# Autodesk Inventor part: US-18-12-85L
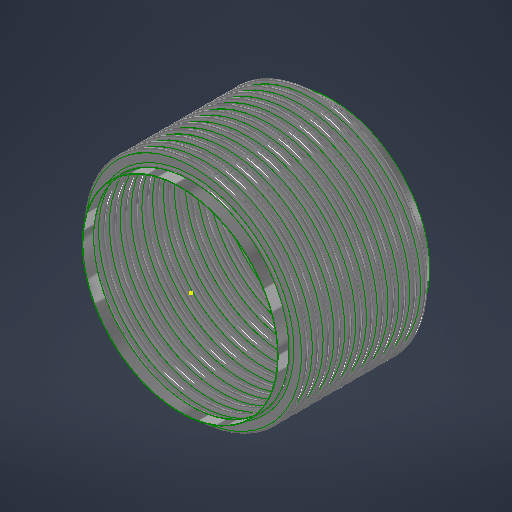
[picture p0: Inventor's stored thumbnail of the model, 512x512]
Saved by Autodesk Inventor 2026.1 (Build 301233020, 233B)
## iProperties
Category: 18 GA (0.048 THICK)
RuleStatus: InUse
Created: 2026-07
Part Number: US-18-12-85L
Project: =STOCK BELLOWS: <Stock Number><SFILL>
Material: ASTM A240-304
Description: =STOCK BELLOWS: <Stock Number>, <SID_> I.D., <SOD_> O.D., <SPLY_> PLY, <Category>, <SNET_CONS> CONS.<PITCH_><STANGENT_> TANGENT<SFILL>
Document SubType Name: Sheet Metal
Designer: LC
Stock Number: U.S-18-12-85L
Surface Area: 659.127 cm^2
Volume: 56.61 cm^3
Sheet Metal Rule: Default
Appearance: STAINLESS STEEL
NET_TUBE: 3.428
COUNTER: 1.500
PBAR: 1.214
PSET: 5.356
PLY: 2
CONS: 2
THK: 0.036
ID: 4.500
OD: 5.500
CONS_: 2
TANGENT: 0.500
PITCH: 0.375
BELLOWS_UPSET: 0.000
NET_CONS: 2
S_CONS: 0
Description_Units: 0
ID_M: 114.30 mm
OD_M: 139.70 mm
THK_M: 0.91 mm
ID_U: 4.500 in
OD_U: 5.500 in
THK_U: 0.036 in
TANGENT2: 0.500
d79: 1.000
d82: 1.000
d83: 26.000
d84: 24.000
d80: 2.571
d81: 10
SID: 2.375
SCONS_: 12
SPITCH: 0.250
SBELLOWS_UPSET: 0.000
SNET_CONS: 12
SS_CONS: 0
SCONS: 8
d174: 8
d177: 0.018
d178: 2.375
d179: 3.000
d180: 0.375
d181: 1.000
d182: 0.000
d190: 8
d191: 1
d192: 1
d193: 8
d194: 0
PART_NUMBER: U.S-18-12-85L
PRESSURE: 85
SIZE: 18.00
STANGENT_: 1.000
d214: 8
d217: 0.030
d218: 6.625
d219: 8.125
d220: 0.500
d221: 1.000
d222: 0.000
d230: 8
d231: 1
d232: 1
d233: 8
d234: 0
STANGENT: 4.000
SPLY_: 1
STHK_: 0.048
SID_: 18.000
SOD_: 20.500
SPITCH_: 1.000
STANGENT__: 1.000
SBELLOWS_UPSET_: 0.000
SDIFF_TAN: 1.000
TAN_TO_TAN: 0.750 in
d252: 2
d275: 2
d287: 0.050
d289: 0.500
d290: 0.000
d263: 2
d265: 1
d268: 2
d269: 0
d286: 2
d288: 1
d291: 2
d292: 0
SOD_NECK: 18 1/8
CFILL: .
SFILL: .
PITCH_: =, <SPITCH_> PITCH,
SREROLL: 0.750
MATTABLE: 20 GA (0.036 THICK)
MESH: ,
CSECT: 2
Author: LC
Keywords: 20 GA (0.036 THICK)
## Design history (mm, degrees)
sketch "Sketch2"
  geometry: L1 (0, -183.595)-(0, 600.956) reference; L2 (58.979, 0)-(57.15, 0); L3 (60.446, -1.467)-(66.554, -1.467); L4 (60.446, -3.296)-(66.554, -3.296); L5 (66.554, -8.058)-(60.446, -8.058); L6 (66.554, -6.229)-(60.446, -6.229); L7 (58.979, -9.525)-(57.15, -9.525); L8 (60.446, 0)-(60.446, -9.525); L9 (66.554, -4.762)-(69.85, -4.763); L10 (57.15, 0)-(57.15, -9.525); L11 (20.376, 102.841)-(20.376, 101.926); L12 (58.262, 488.877)-(58.262, 349.177); L13 (58.262, 479.352)-(58.262, 339.652); L14 (93.133, -58.817)-(93.133, -71.517); L15 (118.746, -66.401)-(118.746, -66.401); L16 (66.554, -6.229)-(66.554, -8.058); L17 (60.446, -6.229)-(60.446, -8.058); L18 (60.446, -7.144)-(66.554, -7.144); L19 (69.85, 0)-(69.85, -9.525); L20 (-66.554, -6.229)-(-66.554, -8.058); L21 (-66.554, -1.467)-(-60.446, -1.467); L22 (-66.554, -3.296)-(-60.446, -3.296); L23 (-60.446, -6.229)-(-66.554, -6.229); L24 (-66.554, -7.144)-(-60.446, -7.144); L25 (-60.446, -8.058)-(-66.554, -8.058); L26 (-60.446, -6.229)-(-60.446, -8.058); L27 (-57.15, -2.522)-(-57.15, -12.047); L28 (-60.446, -4.763)-(-57.15, -4.763); L29 (-66.554, 3.828)-(-66.554, -9.525); L30 (-68.021, 0)-(-69.85, 0); L31 (-69.85, 0)-(-69.85, -9.525); L32 (-68.021, -9.525)-(-69.85, -9.525); A1 r 1.467 centre (60.446, 0) between (58.979, 0) and (60.446, -1.467); A2 r 3.296 centre (60.446, 0) between (57.15, 0) and (60.446, -3.296); A3 r 3.296 centre (66.554, -4.762) between (66.554, -8.058) and (66.554, -1.467); A4 r 1.467 centre (66.554, -4.762) between (66.554, -6.229) and (66.554, -3.296); A5 r 1.467 centre (60.446, -9.525) between (60.446, -8.058) and (58.979, -9.525); A6 r 3.296 centre (60.446, -9.525) between (60.446, -6.229) and (57.15, -9.525); A7 r 2.381 centre (66.554, -4.762) between (66.554, -7.144) and (68.936, -4.762); A8 r 2.381 centre (60.446, -9.525) between (60.446, -7.144) and (58.064, -9.525); A9 r 1.467 centre (-66.554, -9.525) between (-66.554, -8.058) and (-68.021, -9.525); A10 r 1.467 centre (-60.446, -4.763) between (-60.446, -6.229) and (-60.446, -3.296); A11 r 2.381 centre (-60.446, -4.763) between (-60.446, -7.144) and (-58.064, -4.763); A12 r 3.296 centre (-60.446, -4.763) between (-60.446, -8.058) and (-60.446, -1.467); A13 r 2.381 centre (-66.554, -9.525) between (-66.554, -7.144) and (-68.936, -9.525); A14 r 3.296 centre (-66.554, -9.525) between (-66.554, -6.229) and (-69.85, -9.525); A15 r 1.467 centre (-66.554, 0) between (-68.021, 0) and (-66.554, -1.467); A16 r 3.296 centre (-66.554, 0) between (-69.85, 0) and (-66.554, -3.296); 10 further points
  constraints: 62 end point, 38 point on circle, 20 tangent, 16 centre point, 12 parallel, 9 midpoint, 7 vertical, 6 coincident, 6 concentric, 6 point on line, 4 equal radius, 4 perpendicular, 3 horizontal, 1 collinear, 1 horizontal alignment, 10 other
  dimensions: "THK" = 0.9144 distance of L11.start L11.end; "ID" = 114.3 distance of L11.end point (20.376, -12.374); "OD" = 139.7 distance of L12.start L12.end; "PITCH" = 9.525 distance of L12.start L13.start; "TANGENT" = 12.7 distance of L14.start L14.end; "BELLOWS_UPSET" = 0 distance of L15.start L15.end; "d43" = 114.3 diameter of L10 L1 (= ID); "d44" = 139.7 diameter of L9.end L1 (= OD); "d45" = 1.8288 distance between parallel lines of L5 L6 (computed from THK, PLY); "d46" = 3.29565 radius of A3 (computed from PITCH, THK, PLY); "UPSET_PITCH" = 9.525 distance of L2.end L7.end (derived); "SIDEWALL_ANGLE" = 0 deg angle of L3 L9 (derived); "CON_GAP" = 2.9337 distance of point (60.446, -6.229) point (60.446, -3.296) (derived); "TAN1" = 3.74046 dimension on A8 (derived); "TAN2" = 3.74046 dimension on A7 (derived); "LEG1" = 6.1087 distance of L18.start L18.end (derived); "d278" = 1.8288 distance between parallel lines of L25 L23 (derived); "d279" = 3.29565 radius of A12 (derived); "d280" = 9.525 distance of L30.end L31.end (derived); "d281" = 360 deg dimension on L21 L28 (derived); "d282" = 2.9337 distance of point (-66.554, -6.229) point (-66.554, -3.296) (derived); "d283" = 3.74046 dimension on A13 (derived); "d284" = 3.74046 dimension on A11 (derived); "d285" = 6.1087 distance of L24.start L24.end (derived); "d293" = 114.3 diameter of L27 L1 (derived); "d294" = 139.7 diameter of L31 L1 (derived)
  node "Sketch Rectangular Pattern1" dims "d31" = 25.4, "ID" = 114.3
  node "Sketch Rectangular Pattern2" dims "d39" = 25.4, "PITCH" = 9.525
revolve "CONS" stored, may be unused: angle "d48" = 90 deg
node "BELLOW MIDPLANE"
pattern_linear "Rectangular Pattern2" dims "d52" = 9.525 (= UPSET_PITCH)
sketch "Sketch5"
  geometry: C1 r 58.979 at (0, 0) reference; C2 r 57.15 at (0, 0) reference
extrude "TANGENT" new body sketch "Sketch5" distance "d53" = 12.7 (= TANGENT); taper "d54" = 0 deg
revolve "SAMETAN" stored, may be unused: angle "d65" = 90 deg
revolve "DIFFTAN" stored, may be unused: angle "d70" = 90 deg
sketch "Sketch9"
  geometry: L1 (58.391, 0)-(-58.391, 0) reference; L2 (0, -17.78)-(0, 17.78) reference; L3 (41.708, 0)-(-41.708, 0); L4 (41.708, -11.906)-(41.708, 11.906); L5 (29.008, -11.906)-(29.008, 11.906); L6 (15.418, 11.906)-(15.418, -11.906); L7 (-29.008, -11.906)-(-29.008, 11.906); L8 (-41.708, -11.906)-(-41.708, 11.906); L9 (40.914, -11.906)-(40.914, 11.906); L10 (41.708, -11.906)-(40.914, -11.906); L11 (41.708, 11.906)-(40.914, 11.906); L12 (15.815, 11.906)-(15.022, 11.906); L13 (15.022, 11.906)-(15.022, -11.906); L14 (15.022, -11.906)-(15.815, -11.906); L15 (15.815, -11.906)-(15.815, 11.906); L16 (-15.815, 11.906)-(-15.815, -11.906); L17 (-15.418, 11.906)-(-15.418, -11.906); L18 (-15.815, -11.906)-(-15.022, -11.906); L19 (-15.022, -11.906)-(-15.022, 11.906); L20 (-15.022, 11.906)-(-15.815, 11.906); L21 (-41.708, -11.906)-(-40.914, -11.906); L22 (-40.914, -11.906)-(-40.914, 11.906); L23 (-40.914, 11.906)-(-41.708, 11.906); L24 (-41.708, 11.906)-(-41.708, -11.906); L25 (41.708, -0.397)-(-41.708, -0.397); L26 (-41.708, -0.397)-(-41.708, 0.397); L27 (-41.708, 0.397)-(41.708, 0.397); L28 (41.708, 0.397)-(41.708, -0.397); L29 (-41.708, 11.906)-(41.708, 11.906); L30 (41.708, 11.906)-(41.708, 12.7); L31 (41.708, 12.7)-(-41.708, 12.7); L32 (-41.708, 12.7)-(-41.708, 11.906); L33 (41.708, -11.906)-(-41.708, -11.906); L34 (-41.708, -11.906)-(-41.708, -12.7); L35 (-41.708, -12.7)-(41.708, -12.7); L36 (41.708, -12.7)-(41.708, -11.906); 30 further points
  constraints: 68 end point, 13 midpoint, 13 parallel, 8 horizontal, 7 perpendicular, 6 equal length, 3 point on line, 2 vertical, 14 other
  dimensions: "d115" = 23.8125 distance of L4.start L4.end (derived); "d116" = 12.7 distance between parallel lines of L4 L5 (derived); "d117" = 13.58962 distance between parallel lines of L5 L6 (derived); "d125" = 44.42645 distance between parallel lines of L7 L6 (derived); "d127" = 12.7 distance between parallel lines of L8 L7 (derived); "d128" = 26.28962 distance between parallel lines of L6 L4 (derived); "d130" = 83.41607 distance between parallel lines of L8 L4 (derived); "RULER_THK" = 0.79375 distance between parallel lines of L4 L9; "d135" = 0.79375 distance of L13.end L14.end (derived); "d138" = 30.83684 distance of L13.end L16.end (derived); "d143" = 0.79375 distance of L22.end L8.end (derived); "d144" = 0.79375 distance between parallel lines of L27 L25 (derived)
extrude "RULER" join sketch "Sketch9" distance "d149" = 0.79375 (derived); taper "d150" = 0 deg
extrude "BARS" join sketch "Sketch9" distance "d151" = 0.79375 (derived); taper "d152" = 0 deg
pattern_linear "Rectangular Pattern4" dims "d155" = 30.83684 (derived)
sketch "Sketch13"
  geometry: L1 (93.149, -52.467)-(93.149, -77.867); L2 (229.819, 0)-(228.6, 0); L3 (229.819, -25.4)-(228.6, -25.4); L4 (253.39, -19.66)-(235.56, -19.66); L5 (253.39, -18.44)-(235.56, -18.44); L6 (253.39, -12.7)-(260.35, -12.7); L7 (235.56, -5.74)-(253.39, -5.74); L8 (235.56, 0)-(235.56, -25.4); L9 (228.6, 0)-(228.6, -25.4); L10 (58.254, -220.206)-(58.254, -740.906); L11 (58.254, -245.606)-(58.254, -766.306); L12 (58.254, -296.406)-(58.254, -817.106); L13 (58.254, -321.806)-(58.254, -842.506); L14 (58.254, -347.206)-(58.254, -867.906); L15 (58.254, -372.606)-(58.254, -893.306); L16 (58.254, -398.006)-(58.254, -918.706); L17 (58.254, -271.006)-(58.254, -791.706); L18 (20.376, 103.145)-(20.376, 101.926); L19 (235.56, -6.96)-(253.39, -6.96); L20 (0, -1082.436)-(0, 300.742) reference; L21 (-46.99, 0)-(281.94, 0) reference; A1 r 5.74 centre (235.56, 0) between (229.819, 0) and (235.56, -5.74); A2 r 5.74 centre (235.56, -25.4) between (235.56, -19.66) and (229.819, -25.4); A3 r 6.96 centre (235.56, -25.4) between (235.56, -18.44) and (228.6, -25.4); A4 r 5.74 centre (253.39, -12.7) between (253.39, -18.44) and (253.39, -6.96); A5 r 6.96 centre (253.39, -12.7) between (253.39, -19.66) and (253.39, -5.74); A6 r 6.96 centre (235.56, 0) between (228.6, 0) and (235.56, -6.96); 6 further points; 1 other entity
  constraints: 38 end point, 15 point on circle, 9 tangent, 6 centre point, 6 parallel, 5 vertical alignment, 4 point on line, 4 vertical, 3 coincident, 3 concentric, 2 collinear, 2 equal radius, 1 horizontal, 1 perpendicular, 23 other
  dimensions: "SBELLOWS_UPSET_" = 0 distance of point (118.762, -66.401) point (118.762, -66.401); "STOTAL_THK_BELLOW__" = 1.2192 distance between parallel lines of L4 L5 (derived); "d224" = 6.9596 radius of A5 (derived); "d225" = 25.4 distance of L2.end L3.end (derived); "SSIDEWALL_ANGLE_" = 360 deg dimension on L7 L6 (derived); "SSCON_GAP_" = 11.4808 distance of point (235.56, -18.44) point (235.56, -6.96) (derived); "d235" = 457.2 diameter of L9 L20 (derived); "d236" = 520.7 diameter of L6.end L20 (derived)
  node "Sketch Rectangular Pattern4" dims "d228" = 25.4
  node "Sketch Rectangular Pattern5" dims "d229" = 25.4
revolve "SBELLOW" stored, may be unused: angle "d197" = 90 deg
pattern_linear "Rectangular Pattern5" dims "d204" = 25.4 (derived)
revolve "STANGENT" stored, may be unused: angle "d240" = 90 deg
revolve "SSAMETAN" stored, may be unused: angle "d241" = 90 deg
revolve "SDIFFTAN" stored, may be unused: angle "d246" = 90 deg
revolve "INVCON" stored, may be unused: angle "d295" = 90 deg
pattern_linear "Rectangular Pattern6" dims "d298" = 9.525 (derived)
revolve "INVTANGENT" stored, may be unused: angle "d302" = 90 deg
revolve "INVSAMETAN" stored, may be unused: angle "d307" = 90 deg
revolve "INVDIFFTAN" stored, may be unused: angle "d312" = 90 deg
sketch "ID BELLOW MOUNT CALC"
  geometry: L1 (44.45, 0)-(38.1, 0); L2 (38.1, 0)-(38.1, 12.7); L3 (38.1, 12.7)-(44.45, 12.7); L4 (44.45, 12.7)-(44.45, 0); L5 (36.513, 12.7)-(34.684, 12.7); L6 (34.684, 12.7)-(34.684, 0); L7 (34.684, 0)-(36.513, 0); L8 (36.513, 0)-(36.513, 12.7); L9 (0, -2.54)-(0, 15.24) reference; L10 (-8.89, 0)-(53.34, 0) reference; 1 further point
  constraints: 16 end point, 5 parallel, 2 collinear, 2 horizontal, 2 perpendicular
  dimensions: "d314" = 12.7 distance of L5.end L6.end (derived); "d315" = 1.8288 distance of L5.start L5.end (derived); "IG" = 1.5875 distance between parallel lines of L2 L8; "PIPE_OD" = 88.9 diameter of L4 L9; "PIPE_WALL" = 6.35 distance of L2.end L3.end; "ID_MT_BELLOW" = 69.3674 diameter of L6 L9 (derived)
revolve "CFILL" stored, may be unused: angle "d320" = 90 deg
pattern_linear "Rectangular Pattern7" dims "d323" = 9.525 (derived)
revolve "SFILL" stored, may be unused: angle "d324" = 90 deg
pattern_linear "Rectangular Pattern8" dims "d327" = 25.4 (derived)
node "STOCK BELLOW MIDPLANE"
sketch "Sketch21"
  geometry: L1 (0, -100.013)-(0, 100.013) reference; L2 (-100.013, 0)-(100.013, 0) reference; L3 (-0.099, 71.437)-(0.099, 71.437); L4 (0.099, 71.437)-(0.099, 55.562); L5 (0.099, 55.562)-(-0.099, 55.562); L6 (-0.099, 55.562)-(-0.099, 71.437); C1 r 55.562 at (0, 0); C2 r 71.437 at (0, 0); 3 further points
  constraints: 8 end point, 2 centre point, 2 coincident, 2 parallel, 2 tangent, 1 horizontal, 1 perpendicular, 1 other
  dimensions: "d329" = 111.125 diameter of C1 (derived); "d330" = 142.875 diameter of C2 (derived); "d331" = 0.19844 distance of L3.start L3.end
extrude "CLAMSHELL" cut sketch "Sketch21" extent not by distance; stored distance "d332" = 0; taper "d333" = 0 deg
pattern_circular "Circular Pattern1" dims angle "d335" = 180 deg (derived)
node "BELLOW"
sketch "Sketch6"
  geometry: L1 (-19.05, 58.979)-(-6.35, 58.979); L2 (-6.35, 58.979)-(-6.35, 57.15); L3 (-6.35, 57.15)-(-19.05, 57.15); L4 (-19.05, 57.15)-(-19.05, 58.979); L5 (2.54, 0)-(-59.69, 0) reference; L6 (-38.1, -108.388)-(-38.1, 156.601) reference; 1 further point
  constraints: 8 end point, 2 parallel, 1 horizontal, 1 perpendicular
  dimensions: "d61" = 12.7 distance of L2.end L3.end (derived); "d62" = 1.8288 distance of L1.end L2.end (derived); "d63" = 114.3 diameter of L3 L5 (derived); "d64" = 19.05 distance between parallel lines of L4 L6 (derived)
sketch "Sketch12"
  geometry: 1 further point
sketch "Sketch14"
  geometry: L1 (-25.4, 229.819)-(0, 229.819); L2 (0, 229.819)-(0, 228.6); L3 (0, 228.6)-(-25.4, 228.6); L4 (-25.4, 228.6)-(-25.4, 229.819); L5 (5.08, 0)-(-30.48, 0) reference; L6 (0, -40.884)-(0, 245.303) reference; 1 further point
  constraints: 8 end point, 2 parallel, 1 collinear, 1 horizontal, 1 perpendicular
  dimensions: "d237" = 1.2192 distance of L3.end L1.start (derived); "d238" = 457.2 diameter of L3 L5 (derived); "d239" = 25.4 distance of L1.start L1.end (derived); "SOD_NECK" = 459.6384 diameter of L1 L5 (derived)
sketch "Sketch15"
  geometry: L1 (-40.884, 0)-(245.303, 0) reference; L2 (228.6, -304.8)-(229.819, -304.8); L3 (229.819, -304.8)-(229.819, -330.2); L4 (229.819, -330.2)-(228.6, -330.2); L5 (228.6, -330.2)-(228.6, -304.8); L6 (0, -398.78)-(0, 81.28) reference; 1 further point
  constraints: 8 end point, 2 parallel, 1 horizontal, 1 perpendicular
  dimensions: "d205" = 25.4 distance of L4.end L2.start (derived); "d206" = 1.2192 distance of L3.end L4.end (derived); "d207" = 457.2 diameter of L5 L6 (derived); "d208" = 304.8 distance between parallel lines of L1 L2 (derived)
node "TANGENT_"
node "SAME_TAN"
sketch "Sketch8"
  geometry: L1 (58.979, -19.05)-(57.15, -19.05); L2 (57.15, -19.05)-(57.15, -31.75); L3 (57.15, -31.75)-(58.979, -31.75); L4 (58.979, -31.75)-(58.979, -19.05); L5 (0, -40.64)-(0, 21.59) reference; L6 (-108.388, 0)-(156.601, 0) reference; 1 further point
  constraints: 8 end point, 2 parallel, 1 horizontal, 1 perpendicular
  dimensions: "d66" = 114.3 diameter of L2 L5 (derived); "TOTAL_THK_BELLOW" = 1.8288 distance of L2.end L3.end (derived); "d68" = 19.05 distance between parallel lines of L1 L6 (derived); "d69" = 12.7 distance of L1.end L2.end (derived)
node "DIFF_TAN"
node "Sketch Rectangular Pattern3" dims "d138" = 30.83684 (derived), "d141" = 25.4
node "SBELLOW_"
node "STANGENT_"
node "SSAME_TAN"
sketch "Sketch16"
  geometry: L1 (229.819, -304.8)-(228.6, -304.8); L2 (228.6, -304.8)-(228.6, -330.2); L3 (228.6, -330.2)-(229.819, -330.2); L4 (229.819, -330.2)-(229.819, -304.8); L5 (0, -398.78)-(0, 81.28) reference; L6 (-40.884, 0)-(245.303, 0) reference; 1 further point
  constraints: 8 end point, 2 parallel, 1 horizontal, 1 perpendicular
  dimensions: "SDIFF_TAN" = 25.4 distance of L3.end L1.start; "d243" = 1.2192 distance of L2.end L3.end (derived); "d244" = 304.8 distance between parallel lines of L1 L6 (derived); "d245" = 457.2 diameter of L2 L5 (derived)
node "SDIFF_TAN"
body "Solid15"
sketch "Sketch17"
  geometry: L1 (69.85, 12.7)-(68.021, 12.7); L2 (68.021, 12.7)-(68.021, 0); L3 (68.021, 0)-(69.85, 0); L4 (69.85, 0)-(69.85, 12.7); L5 (0, -2.54)-(0, 15.24) reference; L6 (-13.97, 0)-(83.82, 0) reference; 2 further points
  constraints: 8 end point, 2 parallel, 1 horizontal, 1 midpoint, 1 perpendicular, 1 point on line
  dimensions: "INVTANGENT" = 12.7 distance of L3.end L1.start (derived); "d300" = 1.8288 distance of L1.start L1.end (derived); "d301" = 139.7 diameter of L4 L5 (derived)
body "Solid16"
sketch "Sketch18"
  geometry: L1 (69.85, -19.05)-(68.021, -19.05); L2 (68.021, -19.05)-(68.021, -31.75); L3 (68.021, -31.75)-(69.85, -31.75); L4 (69.85, -31.75)-(69.85, -19.05); L5 (-13.97, 0)-(83.82, 0) reference; L6 (0, -40.64)-(0, 21.59) reference; 1 further point
  constraints: 8 end point, 2 parallel, 1 horizontal, 1 perpendicular
  dimensions: "d303" = 19.05 distance between parallel lines of L1 L5 (derived); "d304" = 12.7 distance of L3.end L1.start (derived); "d305" = 1.8288 distance of L2.end L3.end (derived); "d306" = 139.7 diameter of L4 L6 (derived)
body "Solid17"
sketch "Sketch19"
  geometry: L1 (69.85, -19.05)-(68.021, -19.05); L2 (68.021, -19.05)-(68.021, -31.75); L3 (68.021, -31.75)-(69.85, -31.75); L4 (69.85, -31.75)-(69.85, -19.05); L5 (0, -40.64)-(0, 21.59) reference; L6 (-13.97, 0)-(83.82, 0) reference; 1 further point
  constraints: 8 end point, 2 parallel, 1 horizontal, 1 perpendicular
  dimensions: "d308" = 12.7 distance of L1.end L2.end (derived); "d309" = 139.7 diameter of L4 L5 (derived); "d310" = 1.8288 distance of L2.end L3.end (derived); "d311" = 19.05 distance between parallel lines of L1 L6 (derived)
body "Solid18"
body "Solid19"
body "Solid20"
other parameters: "BMPL" = -152.4, "PSET" = 136.0424 (computed from OD, THK, PLY) [user parameter], "PBAR" = 30.83684 (= 0.570796 x PITCH + OD - ID) [user parameter; used in 1 equation term], "COUNTER" = 15 [user parameter], "NET_TUBE" = 87.07367 (computed from CONS_, PBAR, TANGENT) [user parameter], "S_CONS" = 0 [user parameter; used in 1 equation term], "ID_M" = 114.3 (= ID) [user parameter], "OD_M" = 139.7 (= OD) [user parameter], "THK_M" = 0.9144 (= THK) [user parameter], "ID_U" = 114.3 (= ID) [user parameter], "OD_U" = 139.7 (= OD) [user parameter], "THK_U" = 0.9144 (= THK) [user parameter], "D_UNITS" = 0 [user parameter], "TANGENT2" = 12.7 [user parameter], "TAN_TO_TAN" = 19.05 [user parameter], "OD_NECK" = 117.9576 [user parameter], "d79" = 25.4, "d80" = 65.29823 [user parameter], "d82" = 25.4, "d83" = 660.4, "d84" = 609.6, "sa_0" = 4, "FRAME_THK" = 0.79375 [user parameter], "CON_FLAT" = 13.58962 [user parameter], "SID" = 60.325 [user parameter], "SPITCH" = 6.35 [user parameter], "STANGENT_" = 25.4 [user parameter], "SBELLOWS_UPSET" = 0 [user parameter], "SS_CONS" = 0 [user parameter], "STAN_TO_TAN_" = 304.8 [user parameter], "d100" = 1.2192 [user parameter], "d191" = 25.4 [user parameter], "d194" = 0 [user parameter], "STANGENT" = 101.6 [user parameter], "d234" = 0 [user parameter], "SUPSET_PITCH_" = 25.4 [user parameter], "d269" = 0 [user parameter], "d287" = 1.27, "d289" = 12.7, "d290" = 0, "d292" = 0 [user parameter], "Thickness" = 3.048 (derived), "KFactor" = 4.4, "BendRadius" = 3.048 (derived), "BendReliefWidth" = 3.048 (derived), "BendReliefDepth" = 1.524 (derived), "CornerReliefSize" = 12.192 (derived), "SeamGap" = 0.00508, "MinimumRemnant" = 6.096 (derived), "TransitionRadius" = 3.048 (derived), "JacobiRadiusSize" = 3.048 (derived), "GapSize" = 3.048 (derived), "SREROLL" = 19.05 [user parameter], "CUR_STK_PITCH" = 25.4 [user parameter], "d328" = -152.4 (derived), "CSECTDEG" = 180 deg [user parameter]
